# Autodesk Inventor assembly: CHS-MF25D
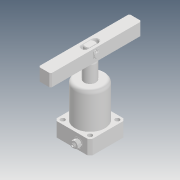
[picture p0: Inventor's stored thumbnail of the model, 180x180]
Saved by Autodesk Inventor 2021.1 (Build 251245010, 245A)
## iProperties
Created: 2019-04
Part Number: CHS-MF25D
Description: STEP AP203
Document SubType Name: Assembly
Designer: user
Title: chs-mf25d_asm.STEP
Revision Number: ÈÎºÎ
Sending System: SolidWorks 2017
Preprocessor: SwSTEP 2.0
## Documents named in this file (9)
- D:\Vault_2016\Projekty\Clamptek\Hydraulic\CHS\CHS-25\Inventor\CHS-MF25D\CHS-MF25D.iam
- D:\Vault_2016\Projekty\Clamptek\Hydraulic\CHS\CHS-25\Inventor\CHS-MF25D\CHS-25D-02_5.ipt
- D:\Vault_2016\Projekty\Clamptek\Hydraulic\CHS\CHS-25\Inventor\CHS-MF25D\CHS-25D-01_5.ipt
- D:\Vault_2016\Projekty\Clamptek\Hydraulic\CHS\CHS-25\Inventor\CHS-MF25D\M6.ipt
- D:\Vault_2016\Projekty\Clamptek\Hydraulic\CHS\CHS-25\Inventor\CHS-MF25D\Öá8µ²È¦.ipt
- D:\Vault_2016\Projekty\Clamptek\Hydraulic\CHS\CHS-25\Inventor\CHS-MF25D\Xiao.ipt
- D:\Vault_2016\Projekty\Clamptek\Hydraulic\CHS\CHS-25\Inventor\CHS-MF25D\CHS-MF25BT.ipt
- D:\Vault_2016\Projekty\Clamptek\Hydraulic\CHS\CHS-25\Inventor\CHS-MF25D\CHS-TXF-01.ipt
- D:\Vault_2016\Projekty\Clamptek\Hydraulic\CHS\CHS-25\Inventor\CHS-MF25D\CHS-MF25-TXF-02.ipt
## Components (9 placed, 9 different names)
1. CHS-25D-02_5_1
2. CHS-25D-01_5_2
3. M6_3
4. Öá8µ²È¦_4
5. Xiao_5
6. Öá8µ²È¦_6
7. CHS-MF25BT_7
8. CHS-TXF-01_8
9. CHS-MF25-TXF-02_9
